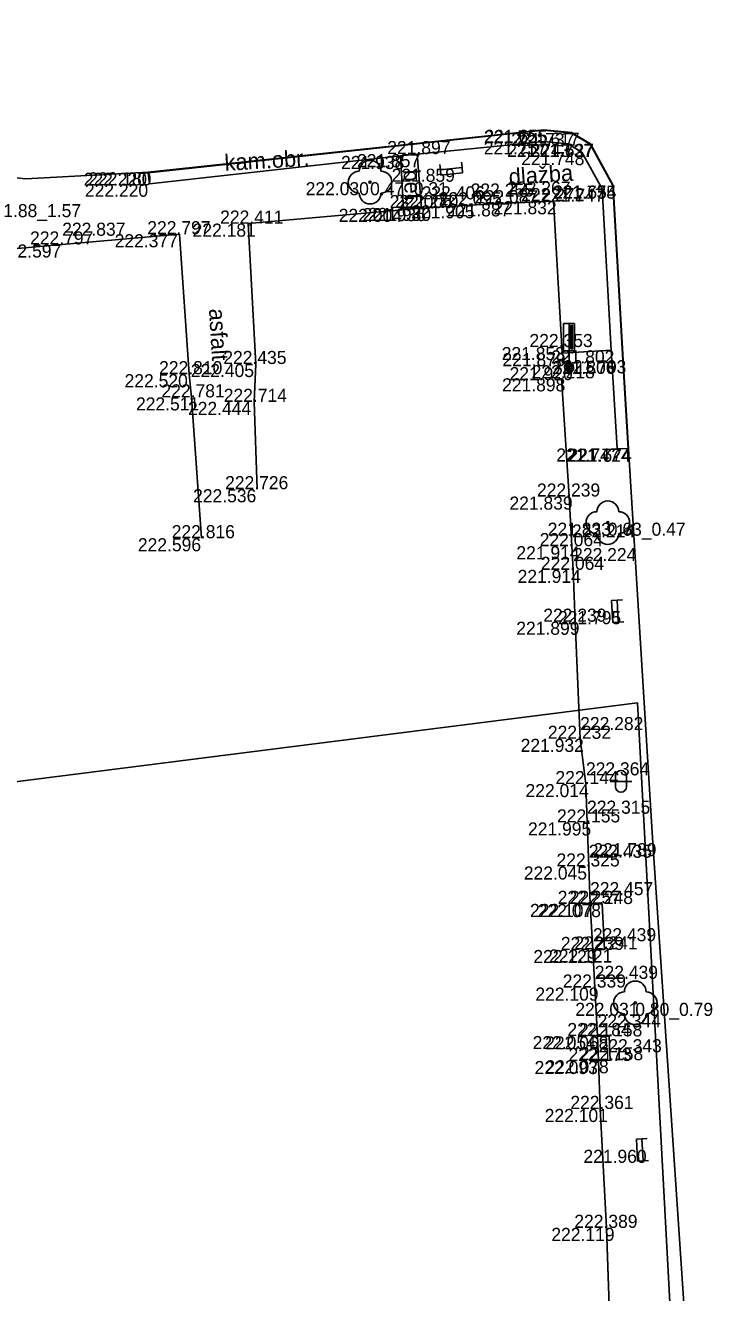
# Model space of a CAD drawing. Extents: x -599516 to -599132, y -1163668 to -1163119.
# Drawn here: x -599301.88 to -599286.02, y -1163526.85 to -1163497.76 of the extents above; entities that cross this region are included whole.
import ezdxf

# ---------------------------------------------------------------- set-up
doc = ezdxf.new("R2010")
doc.units = 0
for name, color, linetype in [('_ZEMERENI OBLAST', 7, 'Continuous'), ('Bod-oznac1', 7, 'Continuous'), ('Bod-oznac2', 7, 'Continuous'), ('Bod-oznac3', 7, 'Continuous'), ('Bod-vyska1', 7, 'Continuous'), ('Bod-vyska2', 7, 'Continuous'), ('Bod-vyska3', 7, 'Continuous'), ('Z_cela-hrobu-dolni-linie', 7, 'Continuous'), ('Z_cela-hrobu-horni-linie', 7, 'Continuous'), ('Z_chodnik', 7, 'Continuous'), ('Z_komunikace', 7, 'Continuous'), ('Z_kultury-znacky', 7, 'Continuous'), ('Z_obvod-kmene-spodek-ve-vysce1_2m', 7, 'Continuous'), ('Z_popis-budov-povrchu', 7, 'Continuous'), ('Z_stromy-kere', 7, 'Continuous'), ('Z_znacky-ostatni-lavicka', 7, 'Continuous'), ('Z_znacky-ostatni-orientacni-sloupek', 7, 'Continuous'), ('Z_zpevnene-plochy', 7, 'Continuous')]:
    doc.layers.add(name, color=color, linetype=linetype)

msp = doc.modelspace()

# ---------------------------------------------------------------- linework, layer by layer
at = {"layer": '_ZEMERENI OBLAST'}
msp.add_lwpolyline([(-599497.946, -1163390.674), (-599491.96, -1163502.01), (-599489.976, -1163538.978), (-599287.834, -1163513.31), (-599283.12, -1163600.69), (-599345.275, -1163603.707), (-599342.31, -1163660.29), (-599277.306, -1163657.294), (-599220.632, -1163654.171)], dxfattribs=at)
at = {"layer": 'Bod-oznac1'}
for p, q in [((-599289.978, -1163500.153), (-599289.978, -1163500.153)), ((-599289.978, -1163500.163), (-599289.978, -1163500.163)), ((-599289.349, -1163500.228), (-599289.349, -1163500.228)), ((-599289.346, -1163500.218), (-599289.346, -1163500.218)), ((-599289.977, -1163500.418), (-599289.977, -1163500.418)), ((-599289.43, -1163500.474), (-599289.43, -1163500.474)), ((-599288.92, -1163500.481), (-599288.92, -1163500.481)), ((-599288.913, -1163500.474), (-599288.913, -1163500.474)), ((-599293.267, -1163500.753), (-599293.267, -1163500.753)), ((-599292.889, -1163500.711), (-599292.889, -1163500.711)), ((-599289.109, -1163500.664), (-599289.109, -1163500.664)), ((-599299.058, -1163501.128), (-599299.058, -1163501.128)), ((-599299.057, -1163501.138), (-599299.057, -1163501.138)), ((-599292.106, -1163501.046), (-599292.106, -1163501.046)), ((-599301.863, -1163501.279), (-599301.863, -1163501.279)), ((-599299.03, -1163501.39), (-599299.03, -1163501.39)), ((-599293.967, -1163501.355), (-599293.967, -1163501.355)), ((-599288.396, -1163501.434), (-599288.396, -1163501.434)), ((-599288.386, -1163501.431), (-599288.386, -1163501.431)), ((-599288.645, -1163501.505), (-599288.645, -1163501.505)), ((-599293.198, -1163501.967), (-599293.198, -1163501.967)), ((-599292.784, -1163501.95), (-599292.784, -1163501.95)), ((-599292.653, -1163501.945), (-599292.653, -1163501.945)), ((-599291.659, -1163501.885), (-599291.659, -1163501.885)), ((-599290.82, -1163501.84), (-599290.82, -1163501.84)), ((-599289.758, -1163501.792), (-599289.758, -1163501.792)), ((-599296.765, -1163502.306), (-599296.765, -1163502.306)), ((-599298.342, -1163502.55), (-599298.342, -1163502.55)), ((-599301.031, -1163502.785), (-599301.031, -1163502.785)), ((-599289.569, -1163505.14), (-599289.569, -1163505.14)), ((-599288.436, -1163505.215), (-599288.436, -1163505.215)), ((-599289.562, -1163505.28), (-599289.562, -1163505.28)), ((-599288.423, -1163505.458), (-599288.423, -1163505.458)), ((-599288.17, -1163505.443), (-599288.17, -1163505.443)), ((-599288.16, -1163505.442), (-599288.16, -1163505.442)), ((-599298.12, -1163505.763), (-599298.12, -1163505.763)), ((-599296.589, -1163505.529), (-599296.589, -1163505.529)), ((-599289.403, -1163505.601), (-599289.403, -1163505.601)), ((-599289.572, -1163505.857), (-599289.572, -1163505.857)), ((-599298.064, -1163506.295), (-599298.064, -1163506.295)), ((-599296.63, -1163506.398), (-599296.63, -1163506.398)), ((-599288.301, -1163507.468), (-599288.301, -1163507.468)), ((-599288.046, -1163507.474), (-599288.046, -1163507.474)), ((-599288.036, -1163507.473), (-599288.036, -1163507.473)), ((-599296.558, -1163508.403), (-599296.558, -1163508.403)), ((-599289.403, -1163508.572), (-599289.403, -1163508.572)), ((-599288.513, -1163509.171), (-599288.513, -1163509.171)), ((-599297.836, -1163509.528), (-599297.836, -1163509.528)), ((-599289.336, -1163509.711), (-599289.336, -1163509.711)), ((-599289.308, -1163510.254), (-599289.308, -1163510.254)), ((-599288.287, -1163511.202), (-599288.287, -1163511.202)), ((-599289.258, -1163511.445), (-599289.258, -1163511.445)), ((-599289.147, -1163514.133), (-599289.147, -1163514.133)), ((-599289.014, -1163515.172), (-599289.014, -1163515.172)), ((-599288.989, -1163516.052), (-599288.989, -1163516.052)), ((-599287.478, -1163516.528), (-599287.478, -1163516.528)), ((-599288.949, -1163517.063), (-599288.949, -1163517.063)), ((-599288.92, -1163517.922), (-599288.92, -1163517.922)), ((-599288.639, -1163517.925), (-599288.639, -1163517.925)), ((-599288.855, -1163518.98), (-599288.855, -1163518.98)), ((-599288.586, -1163518.968), (-599288.586, -1163518.968)), ((-599288.811, -1163519.843), (-599288.811, -1163519.843)), ((-599287.882, -1163520.193), (-599287.882, -1163520.193)), ((-599288.746, -1163520.956), (-599288.746, -1163520.956)), ((-599288.482, -1163520.964), (-599288.482, -1163520.964)), ((-599288.724, -1163521.528), (-599288.724, -1163521.528)), ((-599288.462, -1163521.511), (-599288.462, -1163521.511)), ((-599288.689, -1163522.629), (-599288.689, -1163522.629)), ((-599287.719, -1163523.567), (-599287.719, -1163523.567)), ((-599288.546, -1163525.359), (-599288.546, -1163525.359))]:
    msp.add_line(p, q, dxfattribs=at)
at = {"layer": 'Bod-oznac2'}
for p, q in [((-599292.889, -1163500.711), (-599292.889, -1163500.711)), ((-599292.784, -1163501.95), (-599292.784, -1163501.95)), ((-599292.653, -1163501.945), (-599292.653, -1163501.945)), ((-599291.659, -1163501.885), (-599291.659, -1163501.885)), ((-599290.82, -1163501.84), (-599290.82, -1163501.84)), ((-599289.758, -1163501.792), (-599289.758, -1163501.792)), ((-599296.765, -1163502.306), (-599296.765, -1163502.306)), ((-599298.342, -1163502.55), (-599298.342, -1163502.55)), ((-599301.031, -1163502.785), (-599301.031, -1163502.785)), ((-599289.569, -1163505.14), (-599289.569, -1163505.14)), ((-599298.12, -1163505.763), (-599298.12, -1163505.763)), ((-599296.589, -1163505.529), (-599296.589, -1163505.529)), ((-599289.572, -1163505.857), (-599289.572, -1163505.857)), ((-599298.064, -1163506.295), (-599298.064, -1163506.295)), ((-599296.63, -1163506.398), (-599296.63, -1163506.398)), ((-599296.558, -1163508.403), (-599296.558, -1163508.403)), ((-599289.403, -1163508.572), (-599289.403, -1163508.572)), ((-599297.836, -1163509.528), (-599297.836, -1163509.528)), ((-599289.336, -1163509.711), (-599289.336, -1163509.711)), ((-599289.308, -1163510.254), (-599289.308, -1163510.254)), ((-599289.258, -1163511.445), (-599289.258, -1163511.445)), ((-599289.147, -1163514.133), (-599289.147, -1163514.133)), ((-599289.014, -1163515.172), (-599289.014, -1163515.172)), ((-599288.989, -1163516.052), (-599288.989, -1163516.052)), ((-599288.949, -1163517.063), (-599288.949, -1163517.063)), ((-599288.92, -1163517.922), (-599288.92, -1163517.922)), ((-599288.639, -1163517.925), (-599288.639, -1163517.925)), ((-599288.855, -1163518.98), (-599288.855, -1163518.98)), ((-599288.586, -1163518.968), (-599288.586, -1163518.968)), ((-599288.811, -1163519.843), (-599288.811, -1163519.843)), ((-599288.746, -1163520.956), (-599288.746, -1163520.956)), ((-599288.482, -1163520.964), (-599288.482, -1163520.964)), ((-599288.724, -1163521.528), (-599288.724, -1163521.528)), ((-599288.462, -1163521.511), (-599288.462, -1163521.511)), ((-599288.689, -1163522.629), (-599288.689, -1163522.629)), ((-599288.546, -1163525.359), (-599288.546, -1163525.359))]:
    msp.add_line(p, q, dxfattribs=at)
at = {"layer": 'Bod-oznac3'}
for p, q in [((-599292.784, -1163501.95), (-599292.784, -1163501.95)), ((-599291.659, -1163501.885), (-599291.659, -1163501.885)), ((-599290.82, -1163501.84), (-599290.82, -1163501.84)), ((-599301.031, -1163502.785), (-599301.031, -1163502.785)), ((-599289.336, -1163509.711), (-599289.336, -1163509.711)), ((-599289.308, -1163510.254), (-599289.308, -1163510.254)), ((-599289.147, -1163514.133), (-599289.147, -1163514.133)), ((-599289.014, -1163515.172), (-599289.014, -1163515.172)), ((-599288.989, -1163516.052), (-599288.989, -1163516.052)), ((-599288.949, -1163517.063), (-599288.949, -1163517.063)), ((-599288.92, -1163517.922), (-599288.92, -1163517.922)), ((-599288.855, -1163518.98), (-599288.855, -1163518.98)), ((-599288.811, -1163519.843), (-599288.811, -1163519.843)), ((-599288.746, -1163520.956), (-599288.746, -1163520.956)), ((-599288.724, -1163521.528), (-599288.724, -1163521.528))]:
    msp.add_line(p, q, dxfattribs=at)
at = {"layer": 'Z_cela-hrobu-dolni-linie'}
for points in [[(-599296.765, -1163502.306), (-599292.784, -1163501.95), (-599292.653, -1163501.945), (-599291.659, -1163501.885), (-599290.82, -1163501.84), (-599289.758, -1163501.792), (-599289.569, -1163505.14)], [(-599317.674, -1163504.539), (-599314.403, -1163504.167), (-599310.392, -1163503.801), (-599307.772, -1163503.534), (-599306.11, -1163503.31), (-599305.304, -1163503.202), (-599303.789, -1163503.029), (-599301.031, -1163502.785), (-599298.342, -1163502.55)], [(-599289.572, -1163505.857), (-599289.403, -1163508.572), (-599289.336, -1163509.711), (-599289.308, -1163510.254), (-599289.258, -1163511.445), (-599289.147, -1163514.133), (-599289.014, -1163515.172), (-599288.989, -1163516.052), (-599288.949, -1163517.063), (-599288.92, -1163517.922), (-599288.855, -1163518.98), (-599288.811, -1163519.843), (-599288.746, -1163520.956), (-599288.724, -1163521.528), (-599288.689, -1163522.629), (-599288.546, -1163525.359), (-599288.47, -1163527.374), (-599288.443, -1163528.247)]]:
    msp.add_lwpolyline(points, dxfattribs=at)
at = {"layer": 'Z_cela-hrobu-horni-linie'}
for p, q in [((-599297.836, -1163509.528), (-599298.064, -1163506.295)), ((-599296.558, -1163508.403), (-599296.63, -1163506.398))]:
    msp.add_line(p, q, dxfattribs=at)
for points in [[(-599296.589, -1163505.529), (-599296.765, -1163502.306), (-599292.784, -1163501.95)], [(-599289.569, -1163505.14), (-599289.758, -1163501.792), (-599290.82, -1163501.84), (-599290.82, -1163501.84), (-599291.659, -1163501.885), (-599291.659, -1163501.885), (-599292.653, -1163501.945)], [(-599298.12, -1163505.763), (-599298.342, -1163502.55), (-599301.031, -1163502.785), (-599301.031, -1163502.785), (-599303.789, -1163503.029), (-599303.789, -1163503.029), (-599305.304, -1163503.202), (-599305.304, -1163503.202), (-599306.11, -1163503.31), (-599306.11, -1163503.31), (-599307.772, -1163503.534), (-599307.772, -1163503.534), (-599310.392, -1163503.801), (-599310.392, -1163503.801), (-599314.403, -1163504.167), (-599314.403, -1163504.167), (-599318.395, -1163504.633), (-599318.271, -1163507.81)], [(-599289.572, -1163505.857), (-599289.403, -1163508.572), (-599289.336, -1163509.711), (-599289.336, -1163509.711), (-599289.308, -1163510.254), (-599289.308, -1163510.254), (-599289.258, -1163511.445), (-599289.147, -1163514.133), (-599289.147, -1163514.133), (-599289.014, -1163515.172), (-599289.014, -1163515.172), (-599288.989, -1163516.052), (-599288.989, -1163516.052), (-599288.949, -1163517.063), (-599288.949, -1163517.063), (-599288.92, -1163517.922), (-599288.92, -1163517.922), (-599288.855, -1163518.98), (-599288.855, -1163518.98), (-599288.811, -1163519.843), (-599288.811, -1163519.843), (-599288.746, -1163520.956), (-599288.746, -1163520.956), (-599288.724, -1163521.528), (-599288.724, -1163521.528), (-599288.689, -1163522.629), (-599288.546, -1163525.359), (-599288.443, -1163528.247)]]:
    msp.add_lwpolyline(points, dxfattribs=at)
at = {"layer": 'Z_chodnik'}
for points in [[(-599296.558, -1163508.403), (-599296.63, -1163506.398), (-599296.589, -1163505.529), (-599296.765, -1163502.306)], [(-599298.342, -1163502.55), (-599298.12, -1163505.763), (-599298.064, -1163506.295), (-599297.836, -1163509.528)]]:
    msp.add_lwpolyline(points, dxfattribs=at)
at = {"layer": 'Z_komunikace'}
for points in [[(-599349.383, -1163531.387), (-599349.386, -1163527.731), (-599349.88, -1163519.871), (-599350.071, -1163513.679), (-599350.175, -1163511.974), (-599350.422, -1163507.951), (-599350.33, -1163507.397), (-599350.056, -1163506.984), (-599349.617, -1163506.59), (-599349.045, -1163506.342), (-599340.013, -1163505.384), (-599330.76, -1163504.38), (-599321.537, -1163503.39), (-599317.912, -1163503.036), (-599311.312, -1163502.391), (-599303.679, -1163501.54), (-599302.453, -1163501.219), (-599301.863, -1163501.279), (-599299.058, -1163501.128), (-599289.978, -1163500.153)], [(-599289.978, -1163500.153), (-599289.346, -1163500.218), (-599288.913, -1163500.474), (-599288.386, -1163501.431), (-599288.16, -1163505.442), (-599288.036, -1163507.473), (-599287.478, -1163516.528), (-599286.754, -1163527.316), (-599286.543, -1163530.537), (-599286.137, -1163541.269), (-599285.718, -1163551.502), (-599285.275, -1163558)]]:
    msp.add_lwpolyline(points, dxfattribs=at)
at = {"layer": 'Z_kultury-znacky'}
for p, q in [((-599288.46, -1163515.109), (-599287.96, -1163515.109)), ((-599288.335, -1163514.984), (-599288.335, -1163515.234)), ((-599288.085, -1163514.984), (-599288.085, -1163515.234))]:
    msp.add_line(p, q, dxfattribs=at)
for centre, start, end in [((-599288.21, -1163514.984), 0, 180), ((-599288.21, -1163515.234), 180, 0)]:
    msp.add_arc(centre, 0.125, start, end, dxfattribs=at)
at = {"layer": 'Z_stromy-kere'}
for centre in [(-599293.967, -1163501.355), (-599288.513, -1163509.171), (-599287.882, -1163520.193)]:
    msp.add_circle(centre, 0.025, dxfattribs=at)
for centre, start, end in [((-599293.967, -1163501.105), 0, 180), ((-599294.217, -1163501.355), 90, 270), ((-599293.717, -1163501.355), 270, 90), ((-599293.967, -1163501.605), 180, 0), ((-599288.513, -1163508.921), 0, 180), ((-599288.763, -1163509.171), 90, 270), ((-599288.263, -1163509.171), 270, 90), ((-599288.513, -1163509.421), 180, 0), ((-599287.882, -1163519.943), 0, 180), ((-599288.132, -1163520.193), 90, 270), ((-599287.632, -1163520.193), 270, 90), ((-599287.882, -1163520.443), 180, 0)]:
    msp.add_arc(centre, 0.25, start, end, dxfattribs=at)
at = {"layer": 'Z_znacky-ostatni-lavicka'}
for p, q in [((-599292.368, -1163500.95), (-599292.354, -1163501.074)), ((-599291.872, -1163500.894), (-599291.858, -1163501.018)), ((-599288.176, -1163510.945), (-599288.301, -1163510.952)), ((-599288.148, -1163511.445), (-599288.273, -1163511.452)), ((-599287.608, -1163523.31), (-599287.733, -1163523.317)), ((-599287.58, -1163523.81), (-599287.705, -1163523.817))]:
    msp.add_line(p, q, dxfattribs=at)
for points in [[(-599291.844, -1163501.142), (-599291.858, -1163501.018), (-599292.354, -1163501.074), (-599292.34, -1163501.198)], [(-599288.398, -1163511.459), (-599288.273, -1163511.452), (-599288.301, -1163510.952), (-599288.426, -1163510.959)], [(-599287.83, -1163523.824), (-599287.705, -1163523.817), (-599287.733, -1163523.317), (-599287.858, -1163523.324)]]:
    msp.add_lwpolyline(points, close=True, dxfattribs=at)
at = {"layer": 'Z_znacky-ostatni-orientacni-sloupek'}
for p, q in [((-599289.528, -1163504.601), (-599289.528, -1163505.226)), ((-599289.528, -1163504.601), (-599289.403, -1163504.601)), ((-599289.528, -1163505.226), (-599289.403, -1163505.226)), ((-599289.403, -1163505.226), (-599289.403, -1163505.501))]:
    msp.add_line(p, q, dxfattribs=at)
for points in [[(-599289.403, -1163505.226), (-599289.278, -1163505.226), (-599289.278, -1163504.601), (-599289.403, -1163504.601)], [(-599289.361, -1163505.184), (-599289.321, -1163505.184), (-599289.321, -1163504.644), (-599289.361, -1163504.644)]]:
    msp.add_lwpolyline(points, close=True, dxfattribs=at)
for radius in [0.1, 0.065, 0.03]:
    msp.add_circle((-599289.403, -1163505.601), radius, dxfattribs=at)
at = {"layer": 'Z_zpevnene-plochy'}
msp.add_line((-599292.889, -1163500.711), (-599292.784, -1163501.95), dxfattribs=at)
for points in [[(-599299.057, -1163501.138), (-599289.978, -1163500.163), (-599289.349, -1163500.228), (-599288.92, -1163500.481), (-599288.396, -1163501.434), (-599288.17, -1163505.443), (-599288.046, -1163507.474)], [(-599299.057, -1163501.138), (-599299.03, -1163501.39), (-599293.267, -1163500.753), (-599292.889, -1163500.711), (-599289.977, -1163500.418), (-599289.43, -1163500.474), (-599289.109, -1163500.664), (-599288.645, -1163501.505), (-599288.436, -1163505.215), (-599288.423, -1163505.458), (-599288.301, -1163507.468), (-599288.046, -1163507.474)], [(-599293.198, -1163501.967), (-599293.267, -1163500.753)], [(-599292.784, -1163501.95), (-599292.889, -1163500.711)], [(-599289.569, -1163505.14), (-599289.562, -1163505.28), (-599288.436, -1163505.215)], [(-599288.92, -1163517.922), (-599288.639, -1163517.925), (-599288.586, -1163518.968), (-599288.855, -1163518.98)], [(-599288.855, -1163518.98), (-599288.586, -1163518.968), (-599288.639, -1163517.925), (-599288.92, -1163517.922)], [(-599288.746, -1163520.956), (-599288.482, -1163520.964), (-599288.462, -1163521.511), (-599288.724, -1163521.528)], [(-599288.746, -1163520.956), (-599288.482, -1163520.964), (-599288.462, -1163521.511), (-599288.724, -1163521.528)]]:
    msp.add_lwpolyline(points, dxfattribs=at)

# ---------------------------------------------------------------- texts
at = {"layer": 'Bod-vyska1'}
for s, p in [('221.755', (-599291.357, -1163500.463)), ('221.655', (-599291.344, -1163500.453)), ('221.737', (-599290.73, -1163500.528)), ('221.617', (-599290.61, -1163500.518)), ('221.757', (-599291.358, -1163500.718)), ('221.743', (-599290.821, -1163500.774)), ('221.737', (-599290.301, -1163500.781)), ('221.627', (-599290.281, -1163500.774)), ('221.938', (-599294.633, -1163501.053)), ('221.857', (-599294.268, -1163501.011)), ('221.748', (-599290.5, -1163500.964)), ('222.220', (-599300.537, -1163501.438)), ('222.180', (-599300.434, -1163501.428)), ('221.859', (-599293.472, -1163501.346)), ('222.220', (-599300.51, -1163501.69)), ('222.030', (-599295.445, -1163501.655)), ('221.735', (-599289.775, -1163501.734)), ('221.654', (-599289.764, -1163501.731)), ('221.747', (-599290.038, -1163501.805)), ('222.004', (-599294.687, -1163502.267)), ('221.936', (-599294.139, -1163502.25)), ('221.930', (-599294.017, -1163502.245)), ('221.905', (-599293.023, -1163502.185)), ('221.887', (-599292.199, -1163502.14)), ('221.832', (-599291.136, -1163502.092)), ('222.181', (-599298.039, -1163502.606)), ('222.377', (-599299.827, -1163502.85)), ('222.597', (-599302.503, -1163503.085)), ('221.853', (-599290.947, -1163505.44)), ('221.802', (-599289.812, -1163505.515)), ('221.879', (-599290.93, -1163505.58)), ('221.806', (-599289.787, -1163505.758)), ('221.793', (-599289.538, -1163505.743)), ('221.703', (-599289.538, -1163505.742)), ('222.520', (-599299.6, -1163506.063)), ('222.405', (-599298.08, -1163505.829)), ('221.920', (-599290.767, -1163505.901)), ('221.898', (-599290.938, -1163506.157)), ('222.511', (-599299.338, -1163506.595)), ('222.444', (-599298.145, -1163506.698)), ('221.747', (-599289.694, -1163507.768)), ('221.724', (-599289.437, -1163507.774)), ('221.674', (-599289.415, -1163507.773)), ('222.536', (-599298.028, -1163508.703)), ('221.839', (-599290.769, -1163508.872)), ('221.833', (-599289.891, -1163509.471)), ('222.596', (-599299.295, -1163509.828)), ('221.914', (-599290.61, -1163510.011)), ('221.914', (-599290.582, -1163510.554)), ('221.795', (-599289.655, -1163511.502)), ('221.899', (-599290.613, -1163511.745)), ('221.932', (-599290.513, -1163514.433)), ('222.014', (-599290.401, -1163515.472)), ('221.995', (-599290.344, -1163516.352)), ('221.789', (-599288.846, -1163516.828)), ('222.045', (-599290.44, -1163517.363)), ('222.107', (-599290.298, -1163518.222)), ('222.078', (-599290.12, -1163518.225)), ('222.129', (-599290.221, -1163519.28)), ('222.121', (-599289.86, -1163519.268)), ('222.109', (-599290.175, -1163520.143)), ('222.031', (-599289.258, -1163520.493)), ('222.054', (-599290.237, -1163521.256)), ('222.068', (-599289.95, -1163521.264)), ('222.078', (-599289.943, -1163521.811)), ('222.093', (-599290.192, -1163521.828)), ('222.101', (-599289.961, -1163522.929)), ('221.960', (-599289.072, -1163523.867)), ('222.119', (-599289.808, -1163525.659))]:
    msp.add_text(s, height=0.3, dxfattribs=at).set_placement(p)
at = {"layer": 'Bod-vyska2'}
for s, p in [('221.897', (-599293.573, -1163500.711)), ('222.006', (-599293.517, -1163501.95)), ('222.270', (-599293.394, -1163501.945)), ('222.095', (-599292.393, -1163501.885)), ('222.087', (-599291.561, -1163501.84)), ('222.272', (-599290.5, -1163501.792)), ('222.411', (-599297.407, -1163502.306)), ('222.797', (-599299.079, -1163502.55)), ('222.797', (-599301.768, -1163502.785)), ('222.353', (-599290.31, -1163505.14)), ('222.810', (-599298.808, -1163505.763)), ('222.435', (-599297.335, -1163505.529)), ('222.218', (-599290.261, -1163505.857)), ('222.781', (-599298.754, -1163506.295)), ('222.714', (-599297.325, -1163506.398)), ('222.726', (-599297.294, -1163508.403)), ('222.239', (-599290.138, -1163508.572)), ('222.816', (-599298.519, -1163509.528)), ('222.064', (-599290.076, -1163509.711)), ('222.064', (-599290.048, -1163510.254)), ('222.239', (-599289.993, -1163511.445)), ('222.232', (-599289.888, -1163514.133)), ('222.144', (-599289.714, -1163515.172)), ('222.155', (-599289.678, -1163516.052)), ('222.325', (-599289.69, -1163517.063)), ('222.257', (-599289.662, -1163517.922)), ('222.248', (-599289.385, -1163517.925)), ('222.239', (-599289.59, -1163518.98)), ('222.241', (-599289.28, -1163518.968)), ('222.339', (-599289.546, -1163519.843)), ('222.184', (-599289.44, -1163520.956)), ('222.158', (-599289.171, -1163520.964)), ('222.158', (-599289.151, -1163521.511)), ('222.173', (-599289.414, -1163521.528)), ('222.361', (-599289.372, -1163522.629)), ('222.389', (-599289.281, -1163525.359))]:
    msp.add_text(s, height=0.3, dxfattribs=at).set_placement(p)
at = {"layer": 'Bod-vyska3'}
for s, p in [('222.255', (-599291.659, -1163501.685)), ('222.267', (-599290.82, -1163501.64)), ('222.406', (-599292.784, -1163501.75)), ('222.837', (-599301.031, -1163502.585)), ('222.214', (-599289.336, -1163509.511)), ('222.224', (-599289.308, -1163510.054)), ('222.282', (-599289.147, -1163513.933)), ('222.364', (-599289.014, -1163514.972)), ('222.315', (-599288.989, -1163515.852)), ('222.435', (-599288.949, -1163516.863)), ('222.457', (-599288.92, -1163517.722)), ('222.439', (-599288.855, -1163518.78)), ('222.439', (-599288.811, -1163519.643)), ('222.344', (-599288.746, -1163520.756)), ('222.343', (-599288.724, -1163521.328))]:
    msp.add_text(s, height=0.3, dxfattribs=at).set_placement(p)
at = {"layer": 'Z_obvod-kmene-spodek-ve-vysce1_2m'}
for s, p in [('0.47_0.31', (-599293.967, -1163501.655)), ('1.88_1.57', (-599302.383, -1163502.158)), ('0.63_0.47', (-599288.513, -1163509.471)), ('0.80_0.79', (-599287.882, -1163520.493))]:
    msp.add_text(s, height=0.3, dxfattribs=at).set_placement(p)
at = {"layer": 'Z_popis-budov-povrchu'}
for s, rotation, p in [('kam.obr.', 3.4503, (-599297.296, -1163501.096)), ('bet.', 273.4503, (-599293.205, -1163501.074)), ('dlažba', 3.9346, (-599290.773, -1163501.422)), ('asfalt', 273.4503, (-599297.664, -1163504.266))]:
    msp.add_text(s, height=0.375, rotation=rotation, dxfattribs=at).set_placement(p)

doc.saveas('drawing.dxf')
